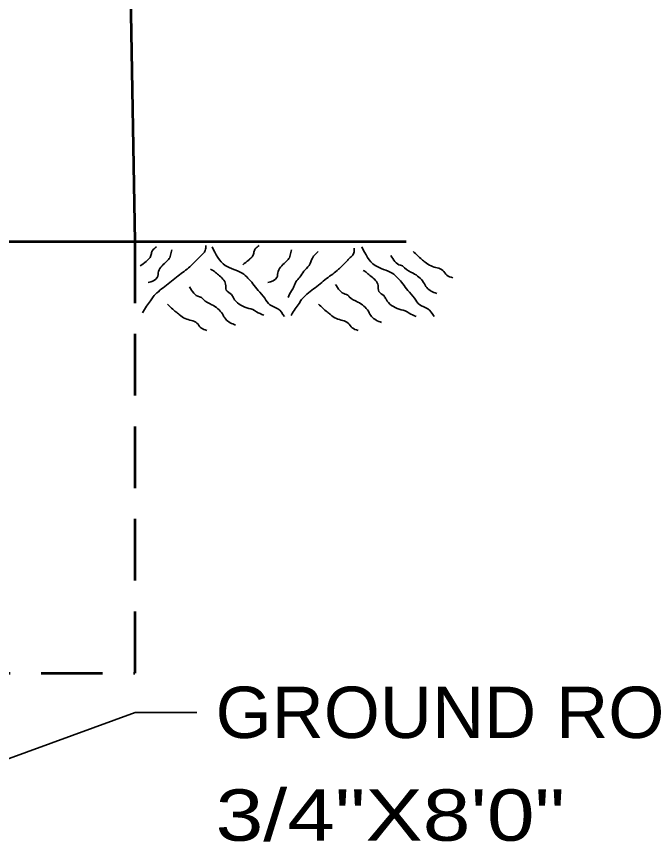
# Model space of a CAD drawing. Extents: x 12366 to 13046, y 9129 to 9570.
# Drawn here: x 12653.81 to 12684.91, y 9367.99 to 9408.13 of the extents above; entities that cross this region are included whole.
import ezdxf

# ---------------------------------------------------------------- set-up
doc = ezdxf.new("R2010")
doc.units = 0
doc.linetypes.add('MEDIUM_DASHED', pattern=[4.5, 3, -1.5])
doc.layers.add('1', color=7, linetype='Continuous', lineweight=53)

msp = doc.modelspace()

# ---------------------------------------------------------------- linework, layer by layer
at = {"layer": '1'}
for p, q in [((12657.031, 9542.164), (12659.562, 9397.186)), ((12650.265, 9397.181), (12672.765, 9397.181))]:
    msp.add_line(p, q, dxfattribs=at)
at = {"layer": '1', "linetype": 'MEDIUM_DASHED'}
for p in [(12659.562, 9397.186), (12650.501, 9376.186)]:
    msp.add_line(p, (12659.562, 9376.186), dxfattribs=at)
at = {"layer": '1', "lineweight": 35}
msp.add_lwpolyline([(12650.192, 9370.84), (12659.589, 9374.26), (12662.589, 9374.26)], dxfattribs=at)
for points in [[(12660.628, 9396.919), (12660.436, 9396.759), (12660.372, 9396.599), (12660.308, 9396.407), (12660.181, 9396.279), (12660.117, 9396.215), (12659.829, 9395.991)], [(12663.015, 9396.981), (12663.015, 9396.853), (12662.951, 9396.661), (12662.823, 9396.533), (12662.695, 9396.405), (12662.439, 9396.149), (12662.247, 9395.957), (12661.671, 9395.509), (12661.352, 9395.253), (12660.712, 9394.741), (12660.456, 9394.485), (12660.328, 9394.293), (12660.136, 9394.038), (12659.944, 9393.718)], [(12663.326, 9396.916), (12663.966, 9396.021), (12664.798, 9395.637), (12665.31, 9395.125), (12665.566, 9394.805), (12665.886, 9394.421), (12666.141, 9394.101), (12666.525, 9393.91), (12666.845, 9393.526)], [(12665.619, 9396.983), (12665.427, 9396.823), (12665.363, 9396.663), (12665.299, 9396.471), (12665.171, 9396.343), (12665.107, 9396.279), (12664.819, 9396.055)], [(12670.245, 9396.853), (12670.245, 9396.725), (12670.181, 9396.533), (12670.053, 9396.405), (12669.925, 9396.277), (12669.669, 9396.021), (12669.477, 9395.829), (12668.901, 9395.381), (12668.581, 9395.125), (12667.941, 9394.613), (12667.685, 9394.357), (12667.557, 9394.165), (12667.366, 9393.91), (12667.174, 9393.59)], [(12670.62, 9396.916), (12671.26, 9396.021), (12672.092, 9395.637), (12672.603, 9395.125), (12672.859, 9394.805), (12673.179, 9394.421), (12673.435, 9394.101), (12673.819, 9393.91), (12674.139, 9393.526)], [(12660.211, 9395.181), (12660.659, 9395.437), (12660.723, 9395.725), (12661.139, 9396.236), (12661.267, 9396.396), (12661.331, 9396.652), (12661.363, 9396.78)], [(12666.033, 9395.181), (12666.481, 9395.437), (12666.545, 9395.725), (12666.961, 9396.236), (12667.089, 9396.396), (12667.153, 9396.652), (12667.185, 9396.78)], [(12668.496, 9396.695), (12668.208, 9396.375), (12668.048, 9396.023), (12667.792, 9395.735), (12667.6, 9395.447), (12667.408, 9395.223), (12667.312, 9394.999), (12667.184, 9394.775), (12667.024, 9394.456)], [(12672.018, 9396.504), (12672.498, 9396.024), (12672.594, 9395.992), (12672.69, 9395.896), (12673.106, 9395.641), (12673.618, 9395.193), (12673.778, 9394.937), (12674.257, 9394.649)], [(12673.117, 9396.697), (12673.533, 9396.313), (12673.693, 9396.185), (12673.981, 9395.993), (12674.556, 9395.769), (12674.748, 9395.545), (12675.036, 9395.417)], [(12663.252, 9395.843), (12663.444, 9395.715), (12663.636, 9395.555), (12663.987, 9395.108), (12664.019, 9394.82), (12664.275, 9394.596), (12664.371, 9394.436), (12665.011, 9393.956), (12665.395, 9393.828), (12665.491, 9393.764), (12665.843, 9393.604)], [(12670.673, 9395.779), (12670.865, 9395.651), (12671.057, 9395.491), (12671.409, 9395.043), (12671.441, 9394.756), (12671.697, 9394.532), (12671.793, 9394.372), (12672.433, 9393.892), (12672.816, 9393.764), (12672.912, 9393.7), (12673.264, 9393.54)], [(12662.229, 9394.969), (12662.709, 9394.489), (12662.805, 9394.457), (12662.901, 9394.361), (12663.317, 9394.105), (12663.829, 9393.657), (12663.989, 9393.401), (12664.469, 9393.113)], [(12669.331, 9395.097), (12669.811, 9394.617), (12669.907, 9394.585), (12670.003, 9394.489), (12670.419, 9394.233), (12670.931, 9393.785), (12671.09, 9393.529), (12671.57, 9393.241)], [(12661.153, 9394.138), (12661.569, 9393.754), (12661.729, 9393.626), (12662.017, 9393.434), (12662.592, 9393.21), (12662.784, 9392.986), (12663.072, 9392.858)], [(12668.51, 9394.138), (12668.926, 9393.754), (12669.086, 9393.626), (12669.374, 9393.434), (12669.95, 9393.21), (12670.142, 9392.986), (12670.43, 9392.858)]]:
    msp.add_spline(points, degree=3, dxfattribs=at)

# ---------------------------------------------------------------- texts
at = {"layer": '1'}
for s, width, p in [('GROUND ROD', 1.05, (12663.497, 9373.023)), ('3/4"X8\'0"', 1.25, (12663.497, 9368.023))]:
    msp.add_text(s, height=2.5, dxfattribs=dict(at, width=width)).set_placement(p)

doc.saveas('drawing.dxf')
